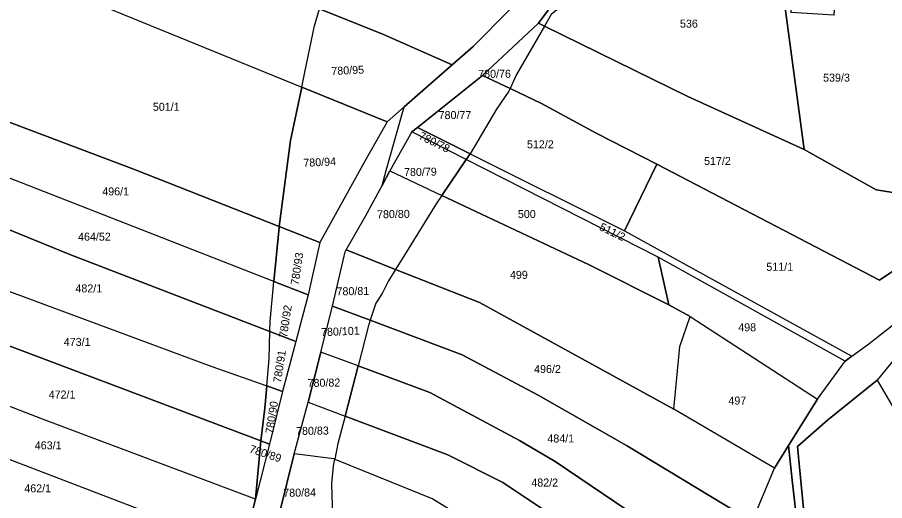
# Model space of a CAD drawing. Extents: x -629983 to -626385, y -1072828 to -1067897.
# Drawn here: x -627261.8 to -626936.7, y -1070029.7 to -1069848.5 of the extents above; entities that cross this region are included whole.
import ezdxf

# ---------------------------------------------------------------- set-up
doc = ezdxf.new("R2010")
doc.units = 0
doc.layers.add('Parcela nároku', color=7, linetype='Continuous')
doc.layers.add('Parcelní číslo', color=7, linetype='Continuous')

msp = doc.modelspace()

# ---------------------------------------------------------------- linework, layer by layer
at = {"layer": 'Parcela nároku'}
for points in [[(-627241.92, -1069814.72), (-627271.63, -1069816.83), (-627267.94, -1069825.76), (-627267.83, -1069828.17), (-627248.42, -1069836.5), (-627155.18, -1069874.63), (-627154, -1069869.04), (-627150.4, -1069851.72), (-627148.6, -1069845.26), (-627224.57, -1069814.81)], [(-627128.21, -1069823.36), (-627077.28, -1069845.64), (-627090.95, -1069859.46), (-627098.75, -1069866.3), (-627124.51, -1069854.91), (-627148.6, -1069845.26), (-627141.19, -1069818.75)], [(-627059.25, -1069840.82), (-627050.65, -1069827.83), (-627049.2, -1069825.55), (-627046.42, -1069827.19), (-627048.74, -1069831.11), (-627040.67, -1069836.11), (-627044.48, -1069840.42), (-627058.25, -1069844.55), (-627061.64, -1069847.48), (-627064.17, -1069851.84), (-627066.48, -1069850.71)], [(-627267.83, -1069828.17), (-627248.42, -1069836.5), (-627155.18, -1069874.63), (-627159.39, -1069894.65), (-627163.63, -1069926.9), (-627217.96, -1069905.51), (-627279.93, -1069882.21), (-627274.63, -1069868.47), (-627269.77, -1069852.06)], [(-627005.67, -1069827.71), (-627008.21, -1069831.82), (-627016.96, -1069832.15), (-627040.67, -1069836.11), (-627044.48, -1069840.42), (-627058.25, -1069844.55), (-627061.64, -1069847.48), (-627064.17, -1069851.84), (-627010.49, -1069878.16), (-626966.86, -1069898.03), (-626975.49, -1069833.73), (-626976.36, -1069828.87)], [(-626955.02, -1069835.66), (-626955.77, -1069847.69), (-626971.74, -1069846.69), (-626970.99, -1069834.66), (-626965.75, -1069834.99), (-626965.93, -1069829.51), (-626976.36, -1069828.87), (-626975.49, -1069833.73), (-626966.86, -1069898.03), (-626939.89, -1069913.2), (-626931.2, -1069914.54), (-626927.45, -1069886.65), (-626924.22, -1069854.62), (-626933.22, -1069831.22), (-626938.2, -1069831.22), (-626958.99, -1069829.94), (-626959.98, -1069835.35)], [(-627154, -1069869.04), (-627150.4, -1069851.72), (-627148.6, -1069845.26), (-627124.51, -1069854.91), (-627098.75, -1069866.3), (-627116.79, -1069882.11), (-627123.18, -1069887.72), (-627155.18, -1069874.63)], [(-627087.46, -1069870.26), (-627066.48, -1069850.71), (-627064.17, -1069851.84), (-627074.68, -1069869.97), (-627077.12, -1069875.2)], [(-627074.68, -1069869.97), (-627077.12, -1069875.2), (-627065.31, -1069880.84), (-627044.87, -1069891.93), (-627022.12, -1069903.5), (-626938.61, -1069947.08), (-626933.99, -1069943.92), (-626920.96, -1069947.32), (-626920.3, -1069945.13), (-626915.31, -1069917), (-626931.2, -1069914.54), (-626939.89, -1069913.2), (-626966.86, -1069898.03), (-627010.49, -1069878.16), (-627064.17, -1069851.84)], [(-627111.85, -1069889.76), (-627087.46, -1069870.26), (-627077.12, -1069875.2), (-627077.6, -1069876.22), (-627082.25, -1069882.95), (-627092.12, -1069899.63)], [(-627155.18, -1069874.63), (-627123.18, -1069887.72), (-627131.73, -1069902.72), (-627148.37, -1069932.91), (-627163.63, -1069926.9), (-627159.39, -1069894.65)], [(-627022.12, -1069903.5), (-627044.87, -1069891.93), (-627065.31, -1069880.84), (-627077.12, -1069875.2), (-627077.6, -1069876.22), (-627082.25, -1069882.95), (-627092.12, -1069899.63), (-627034.14, -1069928.62)], [(-627217.96, -1069905.51), (-627163.63, -1069926.9), (-627163.68, -1069927.25), (-627165.64, -1069947.52), (-627287.9, -1069899.84), (-627279.93, -1069882.21)], [(-627111.85, -1069889.76), (-627092.12, -1069899.63), (-627093.61, -1069901.83), (-627113.99, -1069891.47)], [(-627093.61, -1069901.83), (-627113.99, -1069891.47), (-627122.21, -1069906.12), (-627102.71, -1069915.29)], [(-627287.9, -1069899.84), (-627295.23, -1069915.87), (-627242.19, -1069937.45), (-627167.17, -1069966.33), (-627167.1, -1069962.6), (-627165.64, -1069947.52)], [(-627034.14, -1069928.62), (-626949.01, -1069975.52), (-626951.51, -1069977.49), (-627021.56, -1069938.47), (-627093.61, -1069901.83), (-627092.12, -1069899.63)], [(-627093.61, -1069901.83), (-627102.71, -1069915.29), (-627047.43, -1069941.27), (-627017.53, -1069956.32), (-627021.56, -1069938.47)], [(-626933.99, -1069943.92), (-626938.61, -1069947.08), (-627022.12, -1069903.5), (-627034.14, -1069928.62), (-626949.01, -1069975.52), (-626943.09, -1069971.33), (-626930.93, -1069961.84), (-626924.67, -1069957.02), (-626920.96, -1069947.32)], [(-627138.53, -1069935.73), (-627131.29, -1069923.03), (-627125.12, -1069911.54), (-627122.21, -1069906.12), (-627102.71, -1069915.29), (-627104.85, -1069918.46), (-627115.93, -1069936.49), (-627120.01, -1069943.03)], [(-627295.23, -1069915.87), (-627302.86, -1069937.18), (-627188.97, -1069979.41), (-627168.26, -1069986.73), (-627167.38, -1069976.56), (-627167.17, -1069966.33), (-627242.19, -1069937.45)], [(-627104.85, -1069918.46), (-627115.93, -1069936.49), (-627120.01, -1069943.03), (-627088.59, -1069955.42), (-627015.68, -1069995.42), (-627013.45, -1069971.87), (-627009.62, -1069960.62), (-627017.53, -1069956.32), (-627047.43, -1069941.27), (-627102.71, -1069915.29)], [(-627165.64, -1069947.52), (-627163.68, -1069927.25), (-627163.63, -1069926.9), (-627148.37, -1069932.91), (-627152.83, -1069952.52)], [(-627143.74, -1069956.75), (-627138.95, -1069936.46), (-627138.53, -1069935.73), (-627120.01, -1069943.03), (-627122.71, -1069947.36), (-627125, -1069952.04), (-627127.45, -1069955.66), (-627129.53, -1069962.1)], [(-627302.86, -1069937.18), (-627188.97, -1069979.41), (-627168.26, -1069986.73), (-627168.99, -1069995.1), (-627170.55, -1070007.26), (-627307.82, -1069955.61)], [(-626951.51, -1069977.49), (-627021.56, -1069938.47), (-627017.53, -1069956.32), (-627009.62, -1069960.62), (-626961.77, -1069991.67)], [(-627088.59, -1069955.42), (-627120.01, -1069943.03), (-627122.71, -1069947.36), (-627125, -1069952.04), (-627127.45, -1069955.66), (-627129.53, -1069962.1), (-627095.01, -1069975.09), (-627066.59, -1069990.17), (-627033.45, -1070009.1), (-626986.34, -1070037.52), (-626978, -1070017.56), (-627015.68, -1069995.42)], [(-627167.17, -1069966.33), (-627167.1, -1069962.6), (-627165.64, -1069947.52), (-627152.83, -1069952.52), (-627157.48, -1069970.06)], [(-627307.82, -1069955.61), (-627170.55, -1070007.26), (-627172.55, -1070029.2), (-627252.36, -1069999.23), (-627310.13, -1069976.83)], [(-627148.09, -1069974), (-627143.74, -1069956.75), (-627129.53, -1069962.1), (-627130.33, -1069964.55), (-627134.1, -1069979.16)], [(-627033.45, -1070009.1), (-627066.59, -1069990.17), (-627095.01, -1069975.09), (-627129.53, -1069962.1), (-627130.33, -1069964.55), (-627134.1, -1069979.16), (-627107.13, -1069989.12), (-627073.62, -1070007.14), (-627060.19, -1070015.09), (-627015.45, -1070045.26), (-626986.73, -1070065.45), (-626973.26, -1070046.97), (-626980.83, -1070041.87), (-626986.34, -1070037.52)], [(-627009.62, -1069960.62), (-626961.77, -1069991.67), (-626972.67, -1070009.07), (-626978, -1070017.56), (-627015.68, -1069995.42), (-627013.45, -1069971.87)], [(-627168.26, -1069986.73), (-627167.38, -1069976.56), (-627167.17, -1069966.33), (-627157.48, -1069970.06), (-627162.44, -1069988.79)], [(-627134.1, -1069979.16), (-627148.09, -1069974), (-627152.84, -1069992.86), (-627138.98, -1069998.05)], [(-627310.13, -1069976.83), (-627311.45, -1069996.38), (-627177.32, -1070047.82), (-627172.55, -1070029.2), (-627252.36, -1069999.23)], [(-626986.73, -1070065.45), (-627015.45, -1070045.26), (-627060.19, -1070015.09), (-627073.62, -1070007.14), (-627107.13, -1069989.12), (-627134.1, -1069979.16), (-627138.98, -1069998.05), (-627100.4, -1070012.51), (-627079.87, -1070022.88), (-627056.59, -1070038.48), (-627043.05, -1070049), (-627001.87, -1070083.51)], [(-626958.12, -1069999.59), (-626939.49, -1069984.53), (-626922.33, -1070013.79), (-626933.64, -1070040.63), (-626935.11, -1070046.98), (-626936.62, -1070057.77), (-626938.12, -1070066.39), (-626938.87, -1070068.12), (-626976.78, -1070058.57), (-626970.06, -1070047.13), (-626966.93, -1070034), (-626969.36, -1070009.37)], [(-627168.26, -1069986.73), (-627162.44, -1069988.79), (-627167.24, -1070008.51), (-627170.55, -1070007.26), (-627168.99, -1069995.1)], [(-627152.84, -1069992.86), (-627138.98, -1069998.05), (-627141.62, -1070008.28), (-627142.81, -1070014.22), (-627143.19, -1070014.07), (-627158.09, -1070012.2)], [(-627311.45, -1069996.38), (-627177.32, -1070047.82), (-627181.66, -1070064.26), (-627312.58, -1070017.57)], [(-627138.98, -1069998.05), (-627141.62, -1070008.28), (-627142.81, -1070014.22), (-627106.07, -1070029.02), (-627076.47, -1070047.35), (-627056.84, -1070062.14), (-627027.64, -1070090.16), (-627015.09, -1070101.48), (-627001.87, -1070083.51), (-627043.05, -1070049), (-627056.59, -1070038.48), (-627079.87, -1070022.88), (-627100.4, -1070012.51)], [(-627172.55, -1070029.2), (-627170.55, -1070007.26), (-627167.24, -1070008.51)], [(-626971.36, -1070022.08), (-626969.8, -1070035.12), (-626972.59, -1070045.95), (-626973.26, -1070046.97), (-626980.83, -1070041.87), (-626986.34, -1070037.52), (-626978, -1070017.56), (-626972.67, -1070009.07)], [(-627143.19, -1070014.07), (-627158.09, -1070012.2), (-627163.38, -1070033.87), (-627145.84, -1070040.66), (-627143.56, -1070035.5), (-627143.96, -1070023.4), (-627143.3, -1070016.64), (-627142.81, -1070014.22)], [(-627027.64, -1070090.16), (-627015.09, -1070101.48), (-627029.64, -1070119.37), (-627061.35, -1070085.42), (-627074.63, -1070073.88), (-627092.65, -1070059.98), (-627113.63, -1070046.57), (-627142.64, -1070033.43), (-627143.56, -1070035.5), (-627143.96, -1070023.4), (-627143.3, -1070016.64), (-627142.81, -1070014.22), (-627106.07, -1070029.02), (-627076.47, -1070047.35), (-627056.84, -1070062.14)]]:
    msp.add_lwpolyline(points, close=True, dxfattribs=at)
for points in [[(-627059.25, -1069840.82), (-627066.48, -1069850.71), (-627087.46, -1069870.26), (-627111.85, -1069889.76), (-627113.99, -1069891.47), (-627122.21, -1069906.12), (-627125.12, -1069911.54), (-627123.52, -1069905.89), (-627117.25, -1069883.75), (-627116.79, -1069882.11), (-627098.75, -1069866.3), (-627090.95, -1069859.46), (-627077.28, -1069845.64)], [(-627163.38, -1070033.87), (-627158.09, -1070012.2), (-627152.84, -1069992.86), (-627148.09, -1069974), (-627143.74, -1069956.75), (-627138.95, -1069936.46), (-627138.53, -1069935.73), (-627131.29, -1069923.03), (-627125.12, -1069911.54), (-627123.52, -1069905.89), (-627117.25, -1069883.75), (-627116.79, -1069882.11), (-627123.18, -1069887.72), (-627131.73, -1069902.72), (-627148.37, -1069932.91), (-627152.83, -1069952.52), (-627157.48, -1069970.06), (-627162.44, -1069988.79), (-627167.24, -1070008.51), (-627172.55, -1070029.2), (-627177.32, -1070047.82)], [(-626969.8, -1070035.12), (-626971.36, -1070022.08), (-626972.67, -1070009.07), (-626961.77, -1069991.67), (-626951.51, -1069977.49), (-626949.01, -1069975.52), (-626943.09, -1069971.33), (-626930.93, -1069961.84)], [(-626930.61, -1069973.69), (-626939.49, -1069984.53), (-626958.12, -1069999.59), (-626969.36, -1070009.37), (-626966.93, -1070034)], [(-626930.61, -1069973.69), (-626939.49, -1069984.53), (-626922.33, -1070013.79)]]:
    msp.add_lwpolyline(points, dxfattribs=at)

# ---------------------------------------------------------------- texts
at = {"layer": 'Parcelní číslo'}
for s, p in [('536', (-627013.4, -1069852.36)), ('539/3', (-626959.73, -1069872.61)), ('501/1', (-627211.04, -1069883.55)), ('512/2', (-627070.77, -1069897.62)), ('517/2', (-627004.37, -1069903.86)), ('496/1', (-627230, -1069915.27)), ('500', (-627074.18, -1069923.74)), ('464/52', (-627239.08, -1069932.25)), ('511/1', (-626981.01, -1069943.54)), ('499', (-627077.15, -1069946.56)), ('482/1', (-627240.07, -1069951.64)), ('498', (-626991.55, -1069966.23)), ('473/1', (-627244.45, -1069971.71)), ('496/2', (-627068.09, -1069981.87)), ('472/1', (-627250.1, -1069991.45)), ('497', (-626995.24, -1069993.7)), ('484/1', (-627063.12, -1070007.93)), ('463/1', (-627255.31, -1070010.5)), ('462/1', (-627259.24, -1070026.62)), ('482/2', (-627069.13, -1070024.44))]:
    msp.add_text(s, height=3, dxfattribs=at).set_placement(p)
for s, rotation, p in [('780/95', 2.5783, (-627144.05, -1069870.14)), ('780/76', 0.2291, (-627089.05, -1069871.2)), ('780/77', 0.2291, (-627103.89, -1069886.66)), ('780/78', 333.6907, (-627111.64, -1069893.94)), ('780/94', 2.5783, (-627154.55, -1069904.57)), ('780/79', 0.9167, (-627116.84, -1069908.05)), ('780/80', 0.9167, (-627126.97, -1069923.87)), ('511/2', 334.2834, (-627043.89, -1069928.13)), ('780/93', 81.1881, (-627156.44, -1069949.06)), ('780/81', 0.9167, (-627142.15, -1069952.76)), ('780/92', 81.1881, (-627160.79, -1069968.76)), ('780/101', 2.5783, (-627147.91, -1069968.08)), ('780/91', 81.1881, (-627163, -1069985.69)), ('780/82', 0.9167, (-627153.01, -1069987.12)), ('780/90', 81.1881, (-627165.93, -1070004.81)), ('780/83', 0.9167, (-627157.32, -1070005.13)), ('780/89', 341.7693, (-627175.11, -1070011.58)), ('780/84', 0.9167, (-627162.13, -1070028.32))]:
    msp.add_text(s, height=3, rotation=rotation, dxfattribs=at).set_placement(p)

doc.saveas('drawing.dxf')
